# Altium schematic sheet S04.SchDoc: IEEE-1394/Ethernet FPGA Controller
size 381 x 254 mm; Revision: 3.2; SheetNumber: 4; SheetTotal: 10
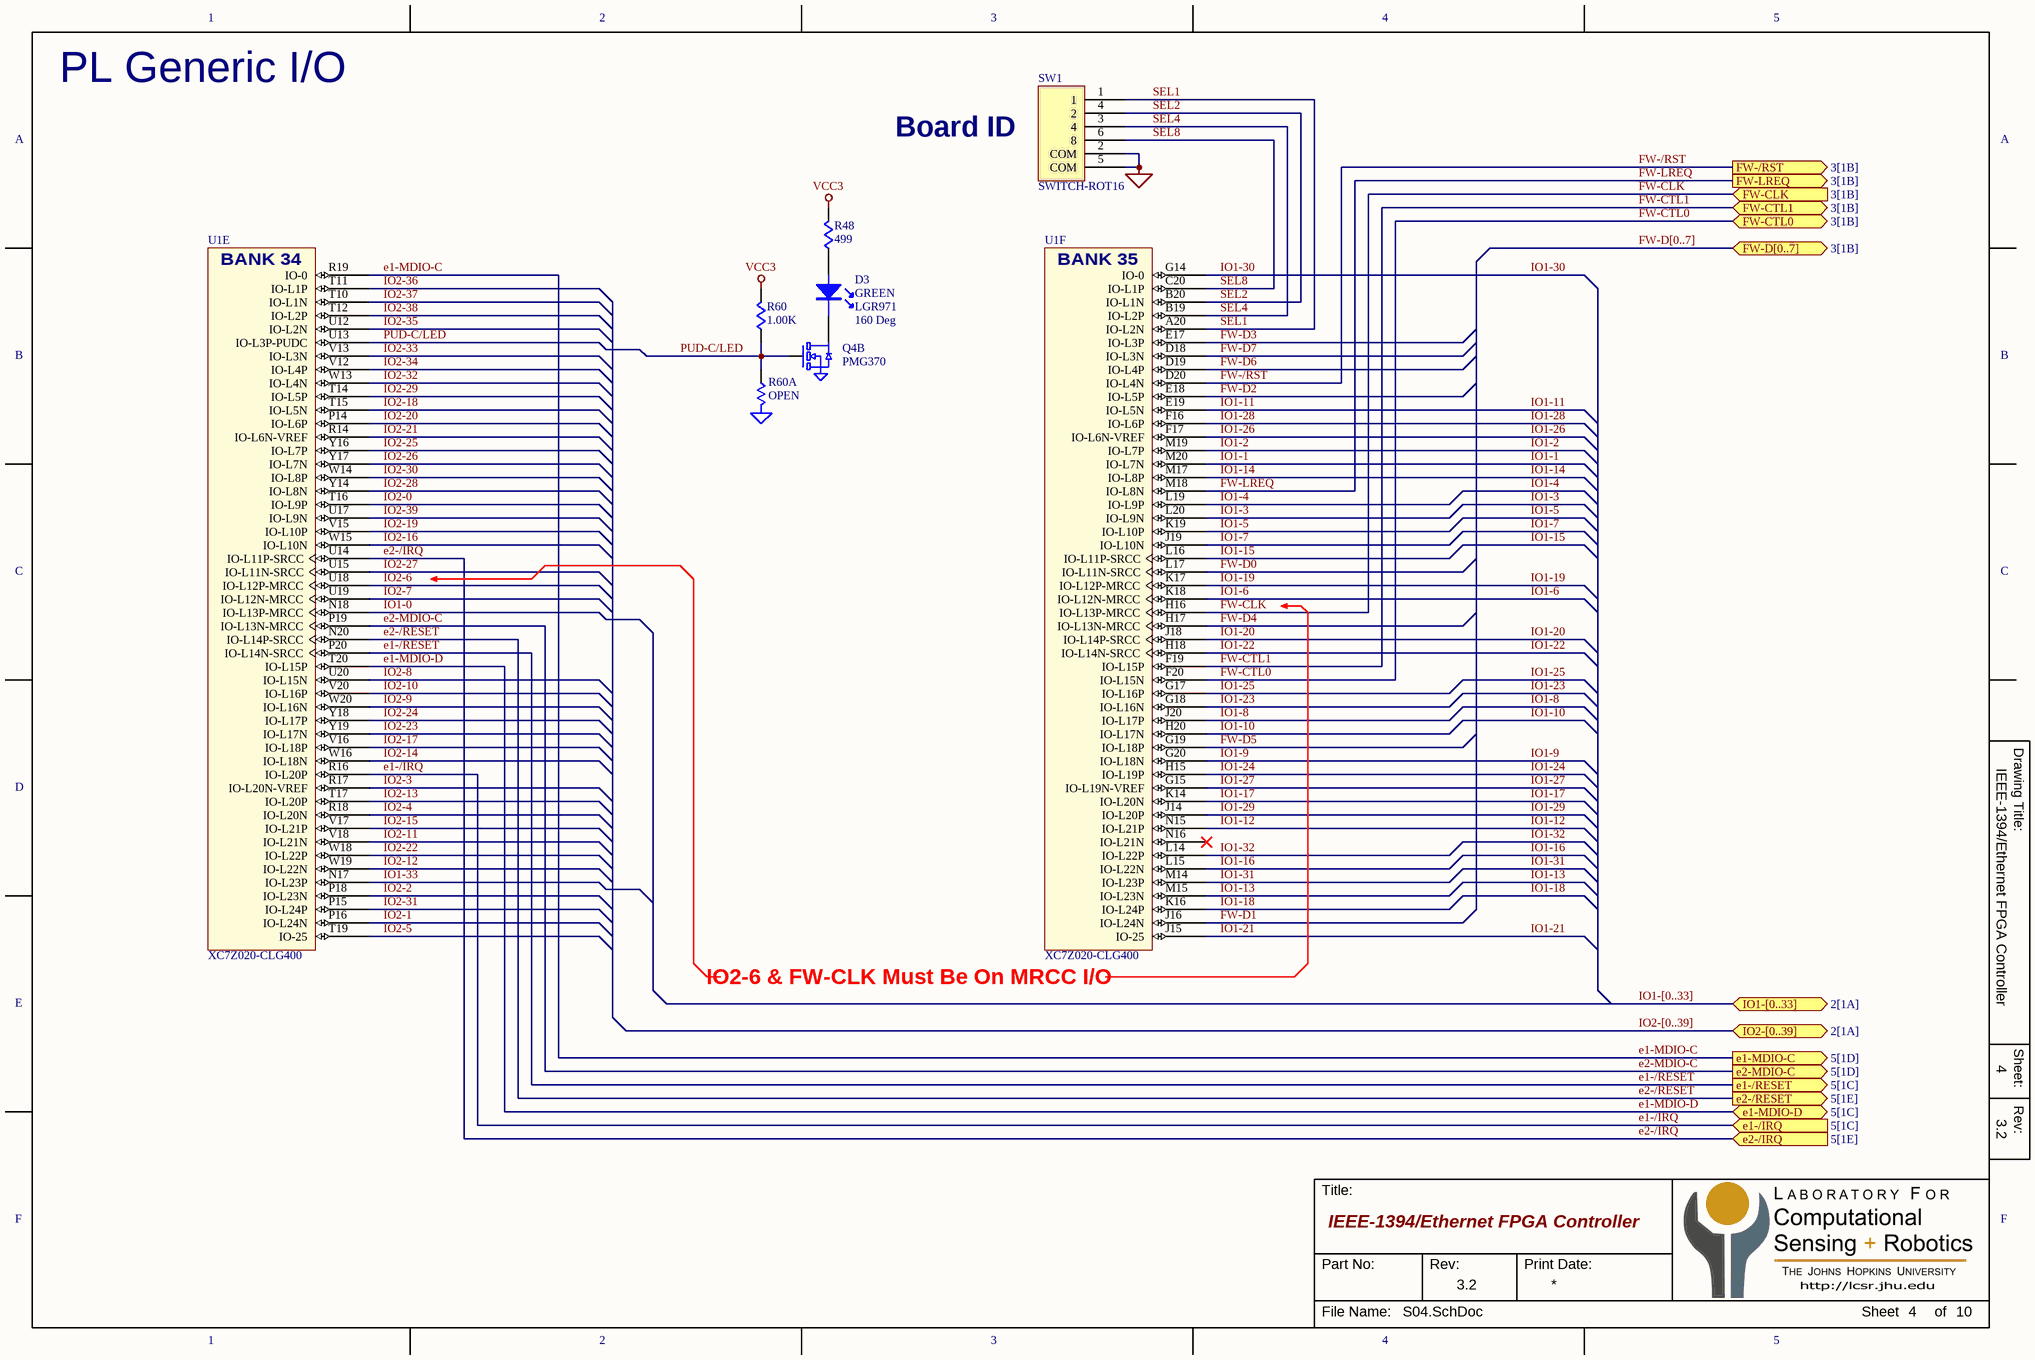
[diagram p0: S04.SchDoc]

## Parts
D3  Color: GREEN  P/N: LGR971  Angle: 160 Deg  [LED-0805]  (hidden comment: LED)
Q4  PMG370  [SC70-6-NP]  (part B of 2)
R48  499  [R0402]
R60  1.00K  [R0402]
R60A  OPEN  [R0402]
SW1  SWITCH-ROT16  [SW-ROT-10MM-TH]
U1  XC7Z020-CLG400  [BGA-400-08mm]  (parts E,F of 9)

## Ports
e1-/IRQ (in, see 5[1C]), e1-/RESET (out, see 5[1C]), e1-MDIO-C (out, see 5[1D]), e1-MDIO-D (bidir, see 5[1C]), e2-/IRQ (in, see 5[1E]), e2-/RESET (out, see 5[1E]), e2-MDIO-C (out, see 5[1D]), FW-/RST (out, see 3[1B]), FW-CLK (in, see 3[1B]), FW-CTL0 (bidir, see 3[1B]), FW-CTL1 (bidir, see 3[1B]), FW-D[0..7] (bidir, see 3[1B]), FW-LREQ (out, see 3[1B]), IO1-[0..33] (bidir, see 2[1A]), IO2-[0..39] (bidir, see 2[1A])

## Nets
GND: Q4.4(S2) R60A.2(GND) SW1.2(COM) SW1.5(COM)
VCC3: R48.2 R60.2
e1-/IRQ: U1.R16(IO-L20P) ; port e1-/IRQ
e1-/RESET: U1.P20(IO-L14N-SRCC) ; port e1-/RESET
e1-MDIO-C: U1.R19(IO-0) ; port e1-MDIO-C
e1-MDIO-D: U1.T20(IO-L15P) ; port e1-MDIO-D
e2-/IRQ: U1.U14(IO-L11P-SRCC) ; port e2-/IRQ
e2-/RESET: U1.N20(IO-L14P-SRCC) ; port e2-/RESET
e2-MDIO-C: U1.P19(IO-L13N-MRCC) ; port e2-MDIO-C
FW-/RST: U1.D20(IO-L4N) ; port FW-/RST
FW-CLK: U1.H16(IO-L13P-MRCC) ; port FW-CLK
FW-CTL0: U1.F20(IO-L15N) ; port FW-CTL0
FW-CTL1: U1.F19(IO-L15P) ; port FW-CTL1
FW-D0: U1.L17(IO-L11N-SRCC)
FW-D1: U1.J16(IO-L24N)
FW-D2: U1.E18(IO-L5P)
FW-D3: U1.E17(IO-L3P)
FW-D4: U1.H17(IO-L13N-MRCC)
FW-D5: U1.G19(IO-L18P)
FW-D6: U1.D19(IO-L4P)
FW-D7: U1.D18(IO-L3N)
FW-LREQ: U1.M18(IO-L8N) ; port FW-LREQ
IO1-0: U1.N18(IO-L13P-MRCC)
IO1-1: U1.M20(IO-L7N)
IO1-2: U1.M19(IO-L7P)
IO1-3: U1.L20(IO-L9N)
IO1-4: U1.L19(IO-L9P)
IO1-5: U1.K19(IO-L10P)
IO1-6: U1.K18(IO-L12N-MRCC)
IO1-7: U1.J19(IO-L10N)
IO1-8: U1.J20(IO-L17P)
IO1-9: U1.G20(IO-L18N)
IO1-10: U1.H20(IO-L17N)
IO1-11: U1.E19(IO-L5N)
IO1-12: U1.N15(IO-L21P)
IO1-13: U1.M15(IO-L23N)
IO1-14: U1.M17(IO-L8P)
IO1-15: U1.L16(IO-L11P-SRCC)
IO1-16: U1.L15(IO-L22N)
IO1-17: U1.K14(IO-L20N)
IO1-18: U1.K16(IO-L24P)
IO1-19: U1.K17(IO-L12P-MRCC)
IO1-20: U1.J18(IO-L14P-SRCC)
IO1-21: U1.J15(IO-25)
IO1-22: U1.H18(IO-L14N-SRCC)
IO1-23: U1.G18(IO-L16N)
IO1-24: U1.H15(IO-L19P)
IO1-25: U1.G17(IO-L16P)
IO1-26: U1.F17(IO-L6N-VREF)
IO1-27: U1.G15(IO-L19N-VREF)
IO1-28: U1.F16(IO-L6P)
IO1-29: U1.J14(IO-L20P)
IO1-30: U1.G14(IO-0)
IO1-31: U1.M14(IO-L23P)
IO1-32: U1.L14(IO-L22P)
IO1-33: U1.N17(IO-L23P)
IO2-0: U1.T16(IO-L9P)
IO2-1: U1.P16(IO-L24N)
IO2-2: U1.P18(IO-L23N)
IO2-3: U1.R17(IO-L20N-VREF)
IO2-4: U1.R18(IO-L20N)
IO2-5: U1.T19(IO-25)
IO2-6: U1.U18(IO-L12P-MRCC)
IO2-7: U1.U19(IO-L12N-MRCC)
IO2-8: U1.U20(IO-L15N)
IO2-9: U1.W20(IO-L16N)
IO2-10: U1.V20(IO-L16P)
IO2-11: U1.V18(IO-L21N)
IO2-12: U1.W19(IO-L22N)
IO2-13: U1.T17(IO-L20P)
IO2-14: U1.W16(IO-L18N)
IO2-15: U1.V17(IO-L21P)
IO2-16: U1.W15(IO-L10N)
IO2-17: U1.V16(IO-L18P)
IO2-18: U1.T15(IO-L5N)
IO2-19: U1.V15(IO-L10P)
IO2-20: U1.P14(IO-L6P)
IO2-21: U1.R14(IO-L6N-VREF)
IO2-22: U1.W18(IO-L22P)
IO2-23: U1.Y19(IO-L17N)
IO2-24: U1.Y18(IO-L17P)
IO2-25: U1.Y16(IO-L7P)
IO2-26: U1.Y17(IO-L7N)
IO2-27: U1.U15(IO-L11N-SRCC)
IO2-28: U1.Y14(IO-L8N)
IO2-29: U1.T14(IO-L5P)
IO2-30: U1.W14(IO-L8P)
IO2-31: U1.P15(IO-L24P)
IO2-32: U1.W13(IO-L4N)
IO2-33: U1.V13(IO-L3N)
IO2-34: U1.V12(IO-L4P)
IO2-35: U1.U12(IO-L2N)
IO2-36: U1.T11(IO-L1P)
IO2-37: U1.T10(IO-L1N)
IO2-38: U1.T12(IO-L2P)
IO2-39: U1.U17(IO-L9N)
PUD-C/LED: Q4.5(G2) R60.1 R60A.1 U1.U13(IO-L3P-PUDC)
SEL1: SW1.1 U1.A20(IO-L2N)
SEL2: SW1.4(2) U1.B20(IO-L1N)
SEL4: SW1.3(4) U1.B19(IO-L2P)
SEL8: SW1.6(8) U1.C20(IO-L1P)
NetD3_1: D3.1(C) Q4.3(D2)
NetD3_2: D3.2(A) R48.1

Not connected (* = marked no-connect by the designer): U1 N16(IO-L21N)*

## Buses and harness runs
bus FW-D[0..7] = port FW-D[0..7]
bus IO1-[0..33] = port IO1-[0..33]
bus IO2-[0..39] = port IO2-[0..39]

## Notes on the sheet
- PL Generic I/O
- Board ID
- IO2-6 & FW-CLK Must Be On MRCC I/O

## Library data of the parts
Q4 = MOSFET-N-DUAL6
R48 R60 = R
R60A = R-GND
